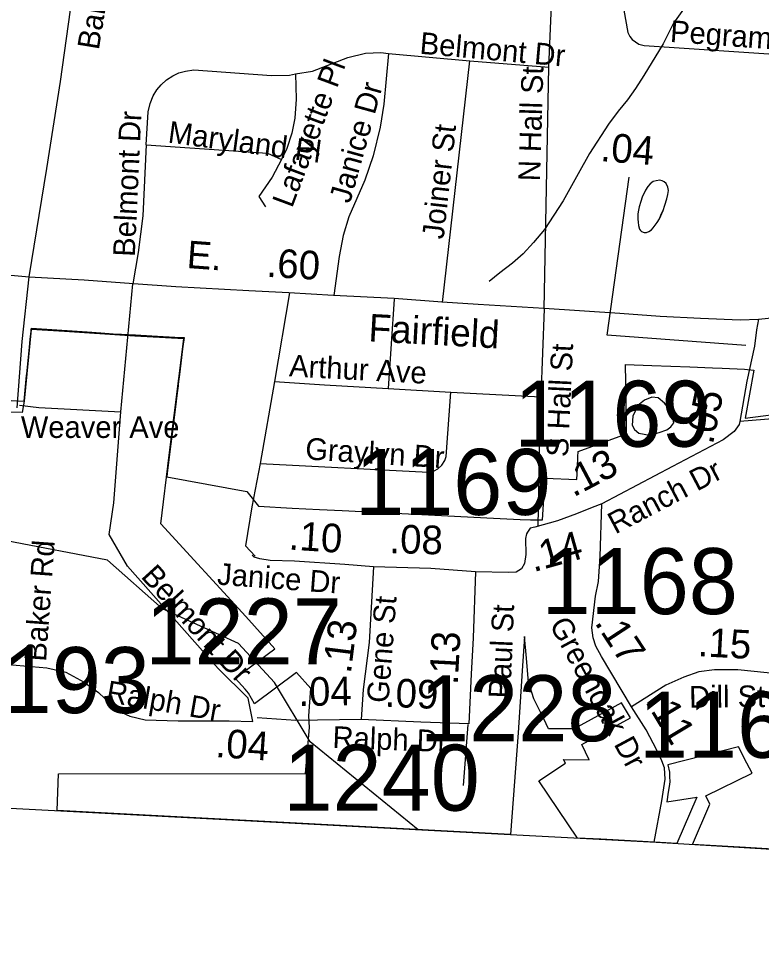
# Model space of a CAD drawing. Extents: x 1662474 to 1856135, y 779280 to 917889.
# Drawn here: x 1711933 to 1715176, y 789845 to 793848 of the extents above; entities that cross this region are included whole.
import ezdxf

# ---------------------------------------------------------------- set-up
doc = ezdxf.new("R2010")
doc.units = 0
for name, color, linetype in [('Cogo Default Point CELL', 7, 'Continuous'), ('Exist Boundary Political City Limit New', 7, 'Continuous'), ('Exist Boundary Political CountyLine', 7, 'Continuous'), ('Exist Hydrographic Misc Water Feature', 7, 'Continuous'), ('Exist Road Non-System Type 51', 7, 'Continuous'), ('Exist Road Non-System Type 51 Label', 7, 'Continuous'), ('Exist Road Primary NC Attributed', 7, 'Continuous'), ('Exist Road Primary NC Label', 7, 'Continuous'), ('Exist Road Secondary Mileage Tenths English Label', 7, 'Continuous'), ('Exist Road Secondary Type 51 Attributed', 7, 'Continuous'), ('Exist Road Secondary Type 51 Label', 7, 'Continuous'), ('Map Preparation Boundary City Limit Buffer Line', 7, 'Continuous'), ('Prop DGN Element Guardrail', 7, 'Continuous'), ('Prop Guardrail', 7, 'Continuous')]:
    doc.layers.add(name, color=color, linetype=linetype)

msp = doc.modelspace()

# ---------------------------------------------------------------- linework, layer by layer
at = {"layer": 'Exist Boundary Political City Limit New'}
for points in [[(1711989.4, 792490.1), (1711958.4, 792176.9), (1711949.4, 792127.5), (1711899.6, 792128.6), (1711739.2, 792144.4), (1711711.2, 792147.1), (1711696, 792037.6), (1711687.4, 791927.7), (1711222.6, 791971.8), (1711122.2, 791981.2), (1711099.5, 791754.2), (1711348.9, 791737.2), (1711348.4, 791735.3), (1711873.5, 791696.8), (1711809, 790781.6), (1711807.5, 790781.6)], [(1711958.4, 792176.9), (1711968.9, 792288.8), (1711969.6, 792297.1), (1711980.4, 792396.9), (1711985.1, 792446.6), (1711988.8, 792483.4), (1711989.4, 792490.1)], [(1711989.4, 792490.1), (1711990, 792496.5), (1712189.4, 792482.6), (1712233.1, 792479.6), (1712293, 792475.4), (1712365.8, 792470.3), (1712382.8, 792469.1), (1712442.6, 792466.4), (1712444, 792466.3), (1712540.8, 792461.1), (1712616.2, 792456.9), (1712656.2, 792454.8), (1712650.1, 792405.1), (1712642.5, 792343.5), (1712637.8, 792305.5), (1712631.1, 792251.9), (1712630.1, 792244.1), (1712629, 792234.6), (1712625, 792202.1), (1712618.8, 792152.4), (1712611.6, 792094.7), (1712605.5, 792045.3), (1712598.8, 791990.9), (1712584.6, 791876.6), (1712580.9, 791846.5), (1712929.4, 791783.3), (1712981.2, 791718.6), (1713127.8, 791710.8), (1713247.6, 791704.7), (1713345.4, 791699.7), (1713488.8, 791692.4), (1713605.6, 791686.5), (1713722.8, 791680.6), (1713976.5, 791667.8), (1714122.5, 791660.9), (1714167.1, 791658.8), (1714219.4, 791658.8), (1714231.8, 791840.6), (1714370.4, 791834.7), (1714372.5, 791885.8), (1714374.2, 791933.6), (1714375.2, 791958.2), (1714586.9, 792035.1), (1714586.8, 792053.1), (1714586.4, 792076.5), (1714585, 792181.4), (1714582.1, 792337.2), (1714697, 792333.1), (1714863.2, 792327.1), (1714962.2, 792322.8), (1715003.4, 792321.7), (1715101, 792317.5), (1715142.4, 792311.9), (1715104.5, 792103.3), (1715306.6, 792129.2)], [(1716380.2, 790152.6), (1715081.1, 790230.6), (1714874.6, 790242.9), (1714950, 790418.9), (1714932.5, 790454.6), (1715134.2, 790553.5), (1715111.2, 790597.9), (1715074.5, 790668.9), (1714767, 790589.4), (1714773.5, 790558), (1714774.2, 790538.6), (1714775.1, 790516.5), (1714771.9, 790495.2), (1714768.4, 790471.2), (1714761.8, 790427.9), (1714893.2, 790448.5), (1714806.4, 790247.1), (1714733.6, 790251.4), (1714474.6, 790265.1), (1714372.1, 790270.5), (1714204.1, 790520.2), (1714319.8, 790597.5), (1714312.2, 790612.9), (1714424, 790611.8), (1714391.1, 790679.4), (1714603.2, 790795.4), (1714565.2, 790860.1), (1714358.4, 790746.9), (1714246.8, 790747.2), (1714225.5, 790790.6), (1714182.6, 790877.9), (1714165.5, 790928.5), (1714159.1, 790948.9), (1714150, 791055.3), (1714141.8, 791150.6), (1714131.6, 791000.4), (1714113.4, 790729.3), (1714080, 790285.9), (1712103.2, 790390.4), (1712108.1, 790550.5), (1713185.5, 790552.5), (1713202.9, 790752.4), (1713200.4, 790803.4), (1713209.4, 790923.9), (1713147.2, 790992.4), (1712963, 790856.2), (1712937.8, 790902.4), (1712922.4, 790919.8), (1712878.6, 790968.1), (1713052.8, 791096.7), (1712925.4, 791237.1), (1712554.5, 791642.4), (1712591.6, 791942.1), (1712654.5, 792449.4), (1712442.1, 792461), (1712134.6, 792480.9), (1711989.4, 792490.1)], [(1711902.6, 792180.4), (1711958.4, 792176.9)]]:
    msp.add_lwpolyline(points, dxfattribs=at)
at = {"layer": 'Exist Boundary Political CountyLine'}
msp.add_lwpolyline([(1690037.5, 791664.5), (1701364.2, 790957.5), (1714716, 790252.3), (1740499.2, 788706.5), (1750629.1, 788065.3), (1759370.2, 787540.1), (1762189.4, 787333), (1768414.3, 786933.6), (1776472.8, 786425.7), (1794607.1, 785397.2), (1814974.6, 784258.7), (1839558.3, 782880.6)], dxfattribs=at)
at = {"layer": 'Exist Hydrographic Misc Water Feature'}
for points in [[(1715151.2, 794379.7), (1715141, 794365.8), (1715053.8, 794246.6), (1714960.6, 794117.5), (1714899.6, 794006), (1714856.7, 793918.3), (1714791.8, 793826.9), (1714746.9, 793737.3), (1714661.5, 793598.1), (1714625, 793542.4), (1714590.6, 793492.7), (1714550.2, 793443.1), (1714507.5, 793385.5), (1714424.3, 793258.2), (1714375.4, 793168.7), (1714310.3, 793051.3), (1714229.2, 792925.9), (1714180.6, 792870.4), (1714136.1, 792820.9), (1714089.6, 792779.3), (1714033.2, 792737.8), (1713986.9, 792700.2)], [(1714719.5, 792957.4), (1714729.7, 792973.3), (1714737.9, 792993.2), (1714746, 793009.1), (1714754.3, 793033), (1714762.5, 793061), (1714766.7, 793079), (1714769, 793097), (1714767, 793111), (1714759.1, 793127.1), (1714751.3, 793135.1), (1714741.3, 793139.2), (1714731.3, 793141.3), (1714715.3, 793139.5), (1714703.2, 793135.6), (1714689.2, 793125.7), (1714679, 793113.8), (1714668.9, 793097.8), (1714658.6, 793076), (1714654.5, 793067.9), (1714648.4, 793048.1), (1714642.1, 793026.1), (1714638, 793010.2), (1714635.9, 792994.2), (1714635.7, 792972.1), (1714637.5, 792958.1), (1714639.4, 792944.1), (1714643.3, 792928.1), (1714647.2, 792922.1), (1714651.2, 792918.1), (1714663.2, 792913.9), (1714673.2, 792913.8), (1714683.1, 792917.7), (1714695.2, 792925.6), (1714703.2, 792933.5), (1714711.4, 792945.4), (1714719.5, 792957.4)], [(1714719.5, 792957.4), (1714729.7, 792973.3), (1714746, 793009.1), (1714754.3, 793033), (1714762.5, 793061), (1714766.7, 793079), (1714769, 793097), (1714767, 793111), (1714759.1, 793127.1), (1714751.3, 793135.1), (1714741.3, 793139.2), (1714731.3, 793141.3), (1714715.3, 793139.5), (1714703.2, 793135.6), (1714689.2, 793125.7), (1714679, 793113.8), (1714668.9, 793097.8), (1714654.5, 793067.9), (1714648.4, 793048.1), (1714642.1, 793026.1), (1714638, 793010.2), (1714635.9, 792994.2), (1714635.7, 792972.1), (1714637.5, 792958.1), (1714639.4, 792944.1), (1714643.3, 792928.1), (1714647.2, 792922.1), (1714651.2, 792918.1), (1714663.2, 792913.9), (1714673.2, 792913.8), (1714683.1, 792917.7), (1714695.2, 792925.6), (1714703.2, 792933.5), (1714711.4, 792945.4), (1714719.5, 792957.4)], [(1714793.3, 792082.4), (1714783.8, 792128.5), (1714752, 792168.8), (1714724.3, 792191.1), (1714696.3, 792195.4), (1714664.2, 792181.6), (1714635.9, 792157.9), (1714613.5, 792112.1), (1714611.2, 792072.1), (1714621, 792054), (1714640.8, 792037.8), (1714686.8, 792029.4), (1714728.9, 792041), (1714763, 792052.7), (1714779.2, 792064.6), (1714793.3, 792082.4)], [(1714793.3, 792082.4), (1714783.8, 792128.5), (1714752, 792168.8), (1714724.3, 792191.1), (1714696.3, 792195.4), (1714664.2, 792181.6), (1714635.9, 792157.9), (1714613.5, 792112.1), (1714611.2, 792072.1), (1714621, 792054), (1714640.8, 792037.8), (1714686.8, 792029.4), (1714728.9, 792041), (1714763, 792052.7), (1714779.2, 792064.6), (1714793.3, 792082.4)], [(1713678.2, 790307.1), (1713206.2, 790690), (1713051.1, 790949.2), (1712894.2, 791119.8), (1712562.1, 791271), (1712322.1, 791482.7), (1710999.1, 791736.1)]]:
    msp.add_lwpolyline(points, dxfattribs=at)
at = {"layer": 'Exist Road Non-System Type 51'}
for p, q in [((1714247.1, 793634.4), (1714260.6, 793950.8)), ((1713548.5, 793694.9), (1713903.4, 793663.1)), ((1713783.9, 792608), (1713903.4, 793663.1)), ((1713903.4, 793663.1), (1714247.1, 793634.4)), ((1714227.8, 792579.6), (1714247.1, 793634.4)), ((1712380.4, 792130.9), (1712432.5, 792689.6)), ((1713115.5, 792649.4), (1713050.4, 792263.6)), ((1713572.1, 792621.9), (1713546.6, 792232.4)), ((1714227.8, 792579.6), (1714212, 792195.9)), ((1713050.4, 792263.6), (1712987.9, 791905.6)), ((1713546.6, 792232.4), (1713820.4, 792217.2)), ((1713820.4, 792217.2), (1714212, 792195.9)), ((1713893.9, 790765.8), (1713873.1, 790500.2))]:
    msp.add_line(p, q, dxfattribs=at)
for points in [[(1714260.6, 793950.8), (1714318.6, 793967.2), (1714465.1, 794001.4), (1714512.9, 794008.8), (1714535.4, 794005.1), (1714548.8, 793990.9), (1714560.4, 793965.9), (1714592.6, 793786.2), (1714600.8, 793769.1), (1714611.5, 793755.2), (1714640.4, 793735.8), (1714662.9, 793730.2), (1715316.1, 793685.9), (1715344.2, 793686.2), (1715366.6, 793675.4), (1715375.8, 793666.8), (1715385.5, 793650.5), (1715390.2, 793619), (1715388.6, 793546.5), (1715393.4, 793535.5), (1715408.9, 793524.5), (1715669.2, 793502.4)], [(1713142.8, 793605.4), (1713215.8, 793617.7), (1713370.1, 793677.5), (1713447.2, 793696.4), (1713515.1, 793699.6), (1713548.5, 793694.9)], [(1713548.5, 793694.9), (1713527.5, 793473), (1713511, 793373.4), (1713481.1, 793247.6), (1713444.1, 793141.2), (1713374.5, 792982), (1713349.9, 792900.4), (1713332.8, 792809.2), (1713309.4, 792638.2)], [(1712490.2, 793295.6), (1712500.2, 793439.7), (1712508.1, 793476.4), (1712522, 793510.4), (1712537.2, 793535.5), (1712555.6, 793557.9), (1712580, 793579.9), (1712607.4, 793597.7), (1712633.9, 793609.8), (1712661.9, 793618.2), (1712698.1, 793622.9), (1713037.8, 793598.5), (1713116.5, 793600.4), (1713142.8, 793605.4)], [(1713142.8, 793605.4), (1713145.4, 793494.9), (1713138.9, 793412.9), (1713126.5, 793346.2), (1713104.6, 793279.4), (1713081.4, 793231.6)], [(1712490.2, 793295.6), (1712476.4, 792985.7), (1712456.1, 792826.6), (1712432.5, 792689.6)], [(1712490.2, 793295.6), (1713019.9, 793258.9), (1713081.4, 793231.6)], [(1713081.4, 793231.6), (1713040.1, 793155.2), (1712981.9, 793070.4), (1713011.5, 793025.5)], [(1713050.4, 792263.6), (1713268.8, 792247.9), (1713546.6, 792232.4)], [(1712987.9, 791905.6), (1713722.9, 791867), (1713746.6, 791873.4), (1713762.9, 791881.8), (1713781.1, 791897.8), (1713793.9, 791918.8), (1713799.4, 791935.9), (1713820.4, 792217.2)], [(1714212, 792195.9), (1714206.5, 792022.7), (1714199.9, 791631.4)], [(1711938.9, 792159.4), (1712022.9, 792150), (1712380.4, 792130.9)], [(1712955.9, 790779.2), (1712935.6, 790880.7), (1712805.5, 791010.9), (1712409.1, 791456.5), (1712329.6, 791595.4), (1712349.6, 791733.7), (1712380.4, 792130.9)], [(1712987.9, 791905.6), (1712952.2, 791715.6), (1712924.6, 791545.8), (1712966.7, 791500.6)], [(1711856.9, 791030.5), (1712057.9, 791013.4), (1712140.1, 790994.1), (1712221, 790951.4), (1712283.4, 790905.7), (1712366.1, 790827.2), (1712419.9, 790802.2), (1712485.9, 790785.9), (1712630.4, 790781.8), (1712853.5, 790781.8), (1712955.9, 790779.2)]]:
    msp.add_lwpolyline(points, dxfattribs=at)
at = {"layer": 'Exist Road Primary NC Attributed'}
for points in [[(1715161.7, 792534.6), (1715304.6, 792549.5), (1715406.5, 792564.5), (1715662.7, 792607.5), (1715792.6, 792629.5), (1716066.8, 792675.4), (1716255.6, 792703.4), (1716394, 792722.4), (1716536.9, 792746.4), (1716657.7, 792765.3), (1716888, 792807.3), (1717037.9, 792839.3), (1717240.2, 792891.2), (1717380, 792926.2), (1717583.9, 792974.1)], [(1711834.2, 792733.6), (1711980.1, 792720.4)], [(1711980.1, 792720.4), (1712221, 792706.3), (1712434.9, 792691.5), (1712619.8, 792678.2), (1712939.3, 792660.2), (1713112.9, 792651.6), (1713308.8, 792639.8), (1713573.2, 792626.5), (1713782.4, 792610.9), (1713938.8, 792599.9), (1714227, 792583.5), (1714556.6, 792560.8), (1714732.6, 792548.3), (1714909.3, 792539.7), (1715082.8, 792532.6), (1715161.7, 792534.6)]]:
    msp.add_lwpolyline(points, dxfattribs=at)
at = {"layer": 'Exist Road Secondary Type 51 Attributed'}
for points in [[(1711980.1, 792720.4), (1712057.3, 793192.1), (1712117.7, 793573.1), (1712168.9, 793949.6), (1712234, 794372.5), (1712271.2, 794651.3), (1712289.2, 794759), (1712329.2, 794912.6), (1712473.9, 795357.1), (1712559.9, 795520.4), (1712593.7, 795605.5), (1712625.8, 795705.1), (1712648.3, 795803), (1712674.7, 795925.5), (1712699.3, 796156.8), (1712781.9, 796663.3), (1712836.2, 796867.3), (1712887.2, 796972.5), (1712944.6, 797071.4), (1713225.3, 797396.5), (1713368.9, 797536.8), (1713589, 797689.8), (1713974.4, 797851.7), (1714335.6, 798017.4)], [(1711927.7, 792148), (1711949.8, 792437), (1711980.1, 792720.4)], [(1715161.7, 792534.6), (1715153.7, 792488.4), (1715144.6, 792417.2), (1715111.3, 792264.2), (1715081.3, 792088.8)], [(1715081.3, 792088.8), (1715077.9, 792075.9), (1715056.5, 792044.9), (1715008, 792008), (1714786.7, 791891.6), (1714478.4, 791728.6)], [(1715392.5, 790977.1), (1715398.5, 791048), (1715438.2, 791308.3), (1715434.4, 791424.6), (1715414.4, 791550.5), (1715387.5, 791734.3), (1715342.5, 792039.7), (1715329.6, 792068.2), (1715303.7, 792094), (1715277.8, 792104.4), (1715241.6, 792101.8), (1715081.3, 792088.8)], [(1714478.4, 791728.6), (1714436.3, 791713.1), (1714368.6, 791686), (1714286, 791654.9), (1714187, 791627), (1714166.1, 791622.4), (1714153.9, 791606.1), (1714149.8, 791598), (1714145.7, 791577.7), (1714147.1, 791508.7), (1714141.7, 791469.4), (1714128.1, 791445), (1714105.1, 791431.5), (1714071.2, 791428.8), (1713927.6, 791432.8)], [(1714608.7, 790843.2), (1714476.9, 791063), (1714452.9, 791107.9), (1714440.9, 791143.9), (1714434.9, 791187.9), (1714450.9, 791325.7), (1714464.6, 791390.5), (1714471.4, 791499.8), (1714478.4, 791728.6)], [(1713482.8, 791453.6), (1713357.1, 791464.6), (1713138.3, 791478.8), (1713031.6, 791482.3), (1712987.2, 791489.5), (1712962.3, 791496.6), (1712952.8, 791505.3)], [(1713482.8, 791453.6), (1713464, 791124.1), (1713438.2, 790918.7), (1713429.4, 790787.8)], [(1713927.6, 791432.8), (1713733.1, 791446.9), (1713482.8, 791453.6)], [(1713927.6, 791432.8), (1713917.2, 791144.4), (1713908.6, 790986.3), (1713898.9, 790769.3)], [(1715392.5, 790977.1), (1715200.7, 790991.1), (1715071.8, 791004), (1714969.9, 791004), (1714901.4, 790996), (1714836.1, 790973.2), (1714757.7, 790937.3), (1714608.7, 790843.2)], [(1714707.7, 790252.8), (1714740.4, 790432.9), (1714755, 790527.1), (1714751.6, 790577.5), (1714740.6, 790607.4), (1714718.6, 790654.4), (1714671.7, 790742.3), (1714608.7, 790843.2)], [(1713429.4, 790787.8), (1713143.9, 790784.1), (1712975.4, 790795.5)], [(1713898.9, 790769.3), (1713688.8, 790776.3), (1713429.4, 790787.8)]]:
    msp.add_lwpolyline(points, dxfattribs=at)
at = {"layer": 'Map Preparation Boundary City Limit Buffer Line'}
for points in [[(1711989.4, 792490.1), (1711958.4, 792176.9), (1711949.4, 792127.5), (1711899.6, 792128.6), (1711739.2, 792144.4), (1711711.2, 792147.1), (1711696, 792037.6), (1711687.4, 791927.7), (1711222.6, 791971.8), (1711122.2, 791981.2), (1711099.5, 791754.2), (1711348.9, 791737.2), (1711348.4, 791735.3), (1711873.5, 791696.8), (1711809, 790781.6), (1711807.5, 790781.6)], [(1711958.4, 792176.9), (1711968.9, 792288.8), (1711969.6, 792297.1), (1711980.4, 792396.9), (1711985.1, 792446.6), (1711988.8, 792483.4), (1711989.4, 792490.1)], [(1711989.4, 792490.1), (1711990, 792496.5), (1712189.4, 792482.6), (1712233.1, 792479.6), (1712293, 792475.4), (1712365.8, 792470.3), (1712382.8, 792469.1), (1712442.6, 792466.4), (1712444, 792466.3), (1712540.8, 792461.1), (1712616.2, 792456.9), (1712656.2, 792454.8), (1712650.1, 792405.1), (1712642.5, 792343.5), (1712637.8, 792305.5), (1712631.1, 792251.9), (1712630.1, 792244.1), (1712629, 792234.6), (1712625, 792202.1), (1712618.8, 792152.4), (1712611.6, 792094.7), (1712605.5, 792045.3), (1712598.8, 791990.9), (1712584.6, 791876.6), (1712580.9, 791846.5), (1712929.4, 791783.3), (1712981.2, 791718.6), (1713127.8, 791710.8), (1713247.6, 791704.7), (1713345.4, 791699.7), (1713488.8, 791692.4), (1713605.6, 791686.5), (1713722.8, 791680.6), (1713976.5, 791667.8), (1714122.5, 791660.9), (1714167.1, 791658.8), (1714219.4, 791658.8), (1714231.8, 791840.6), (1714370.4, 791834.7), (1714372.5, 791885.8), (1714374.2, 791933.6), (1714375.2, 791958.2), (1714586.9, 792035.1), (1714586.8, 792053.1), (1714586.4, 792076.5), (1714585, 792181.4), (1714582.1, 792337.2), (1714697, 792333.1), (1714863.2, 792327.1), (1714962.2, 792322.8), (1715003.4, 792321.7), (1715101, 792317.5), (1715142.4, 792311.9), (1715104.5, 792103.3), (1715306.6, 792129.2)], [(1716380.2, 790152.6), (1715081.1, 790230.6), (1714874.6, 790242.9), (1714950, 790418.9), (1714932.5, 790454.6), (1715134.2, 790553.5), (1715111.2, 790597.9), (1715074.5, 790668.9), (1714767, 790589.4), (1714773.5, 790558), (1714774.2, 790538.6), (1714775.1, 790516.5), (1714771.9, 790495.2), (1714768.4, 790471.2), (1714761.8, 790427.9), (1714893.2, 790448.5), (1714806.4, 790247.1), (1714733.6, 790251.4), (1714474.6, 790265.1), (1714372.1, 790270.5), (1714204.1, 790520.2), (1714319.8, 790597.5), (1714312.2, 790612.9), (1714424, 790611.8), (1714391.1, 790679.4), (1714603.2, 790795.4), (1714565.2, 790860.1), (1714358.4, 790746.9), (1714246.8, 790747.2), (1714225.5, 790790.6), (1714182.6, 790877.9), (1714165.5, 790928.5), (1714159.1, 790948.9), (1714150, 791055.3), (1714141.8, 791150.6), (1714131.6, 791000.4), (1714113.4, 790729.3), (1714080, 790285.9), (1712103.2, 790390.4), (1712108.1, 790550.5), (1713185.5, 790552.5), (1713202.9, 790752.4), (1713200.4, 790803.4), (1713209.4, 790923.9), (1713147.2, 790992.4), (1712963, 790856.2), (1712937.8, 790902.4), (1712922.4, 790919.8), (1712878.6, 790968.1), (1713052.8, 791096.7), (1712925.4, 791237.1), (1712554.5, 791642.4), (1712591.6, 791942.1), (1712654.5, 792449.4), (1712442.1, 792461), (1712134.6, 792480.9), (1711989.4, 792490.1)], [(1711902.6, 792180.4), (1711958.4, 792176.9)]]:
    msp.add_lwpolyline(points, dxfattribs=at)
at = {"layer": 'Prop DGN Element Guardrail'}
msp.add_lwpolyline([(1715106.8, 792419.5), (1714501.4, 792464.8), (1714598.5, 793154.4)], dxfattribs=at)

# ---------------------------------------------------------------- texts
at = {"layer": 'Cogo Default Point CELL'}
for s, p in [('1169', (1714096.2, 791978.5)), ('1169', (1713402.2, 791680.7)), ('1168', (1714215.5, 791247.8)), ('1227', (1712487.7, 791028.2)), ('1193', (1711650.6, 790815.9)), ('1228', (1713685.5, 790693.1)), ('1167', (1714640.1, 790620.9)), ('1240', (1713089.7, 790390))]:
    msp.add_text(s, height=288, dxfattribs=at).set_placement(p)
at = {"layer": 'Exist Road Non-System Type 51 Label'}
for s, rotation, p in [('Pegram Ave', 355.8304, (1714774.3, 793745.3)), ('Belmont Dr', 354.8701, (1713681.7, 793693.9)), ('Lafayette Pl', 69.4915, (1713127.4, 793017)), ('N Hall St', 88.2649, (1714209, 793136)), ('Janice Dr', 74.4822, (1713379.9, 793036.4)), ('Belmont Dr', 87.3553, (1712441.2, 792805.9)), ('Maryland Pl', 352.3577, (1712582.7, 793306.3)), ('Joiner St', 83.7296, (1713788.5, 792881.3)), ('S Hall St', 87.3873, (1714331.1, 791932.2)), ('Arthur Ave', 356.8988, (1713112.8, 792285.6)), ('Graylyn Dr', 356.3146, (1713182.9, 791923.5)), ('Belmont Dr', 312.4177, (1712464.4, 791409.7)), ('Ralph Dr', 350.1354, (1712311.8, 790865.3))]:
    msp.add_text(s, height=95, rotation=rotation, dxfattribs=at).set_placement(p)
msp.add_text('Weaver Ave', height=95, dxfattribs=at).set_placement((1711944.2, 792016.7))
at = {"layer": 'Exist Road Primary NC Label'}
for s, rotation, p in [('E.', 355.7598, (1712665.5, 792758.8)), ('Fairfield', 356.8434, (1713458.9, 792438.7))]:
    msp.add_text(s, height=120, rotation=rotation, dxfattribs=at).set_placement(p)
at = {"layer": 'Exist Road Secondary Mileage Tenths English Label'}
for s, rotation, p in [('.05', 78.2599, (1714963, 791984.9)), ('.10', 356.2816, (1713110.6, 791529.9)), ('.17', 303.2411, (1714444.6, 791210.6)), ('.13', 86.8869, (1713849.9, 790937.6)), ('.15', 356.9892, (1714895.4, 791064.3)), ('.09', 357.4458, (1713530.5, 790844.1)), ('.11', 301.1223, (1714665.6, 790866.4))]:
    msp.add_text(s, height=125, rotation=rotation, dxfattribs=at).set_placement(p)
at = {"layer": 'Exist Road Secondary Type 51 Label'}
for s, rotation, p in [('Baker Rd', 80.6609, (1712283.9, 793707.3)), ('Ranch Dr', 27.7704, (1714537.6, 791594.7)), ('Baker Rd', 85.8448, (1712053.9, 791038.8)), ('Janice Dr', 355.7824, (1712798.5, 791376.8)), ('Gene St', 85.6491, (1713547.9, 790857.9)), ('Paul St', 87.6176, (1714079.2, 790878.3)), ('Greenoak Dr', 298.3055, (1714247.9, 791203.4)), ('Dill St', 0.5786, (1714859.9, 790838.8)), ('Ralph Dr', 357.9, (1713302.6, 790664))]:
    msp.add_text(s, height=95, rotation=rotation, dxfattribs=at).set_placement(p)
at = {"layer": 'Prop DGN Element Guardrail'}
for s, rotation, p in [('.04', 355.4897, (1714470.1, 793225.2)), ('.13', 27.8739, (1714354.5, 791756.5)), ('.08', 358.4487, (1713551.2, 791514.3)), ('.14', 15.7181, (1714180.3, 791430.4)), ('.13', 82.8377, (1713383.5, 790985.3)), ('.04', 0.7479, (1713155.9, 790846.8)), ('.04', 356.1322, (1712790.8, 790624.2))]:
    msp.add_text(s, height=125, rotation=rotation, dxfattribs=at).set_placement(p)
at = {"layer": 'Prop Guardrail'}
msp.add_text('.60', height=125, rotation=356.5732, dxfattribs=at).set_placement((1713013.6, 792720.1))

doc.saveas('drawing.dxf')
